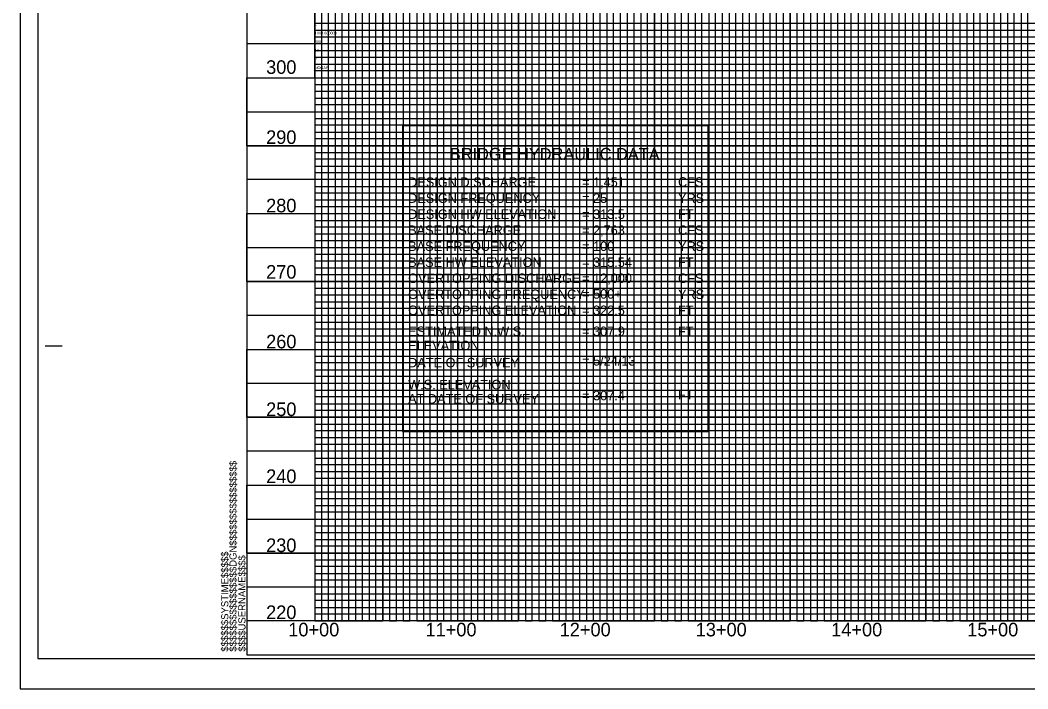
# Model space of a CAD drawing. Extents: x 574125 to 576234, y -56630 to -55530.
# Drawn here: x 574340 to 575082, y -56630 to -56137 of the extents above; entities that cross this region are included whole.
import ezdxf

# ---------------------------------------------------------------- set-up
doc = ezdxf.new("R2010")
doc.units = 0
for name, color, linetype in [('Exist Profile Cell', 7, 'Continuous'), ('Exist Vertical Profile Horizontal Axis Label Major', 7, 'Continuous'), ('Exist Vertical Profile Vertical Axis Label', 7, 'Continuous'), ('Prop Grid Mask', 7, 'Continuous'), ('Prop PFL Text', 7, 'Continuous'), ('Sheet DOT Grid CELL', 7, 'Continuous'), ('Sheet Plot Border Inside CELL', 7, 'Continuous'), ('Sheet Plot Border Outside CELL', 7, 'Continuous'), ('Sheet Profile CELL', 7, 'Continuous'), ('Sheet Profile Grid Major CELL', 7, 'Continuous'), ('Sheet Profile Grid Middle CELL', 7, 'Continuous'), ('Sheet Profile Grid Minor CELL', 7, 'Continuous')]:
    doc.layers.add(name, color=color, linetype=linetype)

msp = doc.modelspace()

# ---------------------------------------------------------------- linework, layer by layer
at = {"layer": 'Exist Profile Cell'}
for q in [(574556.81, -55929.85), (576005.64, -56179.85), (574556.81, -56179.85)]:
    msp.add_line((574556.81, -56179.85), q, dxfattribs=at)
at = {"layer": 'Prop Grid Mask'}
msp.add_lwpolyline([(574621.31, -56440.24), (574846.31, -56440.24), (574846.31, -56215.24), (574621.31, -56215.24)], close=True, dxfattribs=at)
at = {"layer": 'Sheet DOT Grid CELL'}
for p, q in [((574556.81, -55554.85), (574556.81, -56579.85)), ((574606.81, -55554.85), (574606.81, -56579.85)), ((574656.81, -55554.85), (574656.81, -56579.85)), ((574706.81, -55554.85), (574706.81, -56579.85)), ((574756.81, -55554.85), (574756.81, -56579.85)), ((574806.81, -55554.85), (574806.81, -56579.85)), ((574856.81, -55554.85), (574856.81, -56579.85)), ((574906.81, -55554.85), (574906.81, -56579.85)), ((574956.81, -55554.85), (574956.81, -56579.85)), ((575006.81, -55554.85), (575006.81, -56579.85)), ((575056.81, -55554.85), (575056.81, -56579.85)), ((574506.81, -56179.85), (576006.81, -56179.85)), ((574506.81, -56229.85), (576006.81, -56229.85)), ((574506.81, -56279.85), (576006.81, -56279.85)), ((574506.81, -56329.85), (576006.81, -56329.85)), ((574506.81, -56379.85), (576006.81, -56379.85)), ((574506.81, -56429.85), (576006.81, -56429.85)), ((574506.81, -56479.85), (576006.81, -56479.85)), ((574506.81, -56529.85), (576006.81, -56529.85))]:
    msp.add_line(p, q, dxfattribs=at)
at = {"layer": 'Sheet Plot Border Inside CELL'}
msp.add_lwpolyline([(576019.31, -55552.3), (574352.81, -55552.3), (574352.81, -56607.4), (576019.31, -56607.4)], close=True, dxfattribs=at)
at = {"layer": 'Sheet Plot Border Outside CELL'}
msp.add_lwpolyline([(576023.81, -55529.85), (574339.81, -55529.85), (574339.81, -56629.85), (576023.81, -56629.85)], close=True, dxfattribs=at)
at = {"layer": 'Sheet Profile CELL'}
for p, q in [((574339.81, -55529.85), (574339.81, -56629.85)), ((574358.31, -56377.35), (574370.81, -56377.35)), ((576006.81, -56579.85), (574506.81, -56579.85)), ((574506.81, -56604.85), (574506.81, -56604.85)), ((574506.81, -56604.85), (574506.81, -56604.85)), ((574506.81, -56604.85), (574506.81, -56604.85)), ((574506.81, -56604.85), (574506.81, -56604.85)), ((574506.81, -56604.85), (574506.81, -56604.85)), ((574506.81, -56604.85), (574506.81, -56604.85)), ((574339.81, -56629.85), (576023.81, -56629.85))]:
    msp.add_line(p, q, dxfattribs=at)
msp.add_lwpolyline([(576006.81, -55554.85), (574506.81, -55554.85), (574506.81, -56604.85), (576006.81, -56604.85)], close=True, dxfattribs=at)
msp.add_lwpolyline([(574544.31, -56604.85), (574544.31, -56604.85)], dxfattribs=at)
at = {"layer": 'Sheet Profile Grid Major CELL'}
for points in [[(574506.81, -55554.85), (574556.81, -55554.85), (574556.81, -56579.85), (574606.81, -56579.85), (574606.81, -55554.85), (574656.81, -55554.85), (574656.81, -56579.85), (574706.81, -56579.85), (574706.81, -55554.85), (574756.81, -55554.85), (574756.81, -56579.85), (574806.81, -56579.85), (574806.81, -55554.85), (574856.81, -55554.85), (574856.81, -56579.85), (574906.81, -56579.85), (574906.81, -55554.85), (574956.81, -55554.85), (574956.81, -56579.85), (575006.81, -56579.85), (575006.81, -55554.85), (575056.81, -55554.85), (575056.81, -56579.85), (575106.81, -56579.85)], [(576006.81, -56229.85), (574506.81, -56229.85), (574506.81, -56179.85), (576006.81, -56179.85)], [(576006.81, -56329.85), (574506.81, -56329.85), (574506.81, -56279.85), (576006.81, -56279.85)], [(576006.81, -56429.85), (574506.81, -56429.85), (574506.81, -56379.85), (576006.81, -56379.85)], [(576006.81, -56529.85), (574506.81, -56529.85), (574506.81, -56479.85), (576006.81, -56479.85)]]:
    msp.add_lwpolyline(points, dxfattribs=at)
at = {"layer": 'Sheet Profile Grid Middle CELL'}
for points in [[(574581.81, -56579.85), (574581.81, -55554.85), (574631.81, -55554.85), (574631.81, -56579.85), (574681.81, -56579.85), (574681.81, -55554.85), (574731.81, -55554.85), (574731.81, -56579.85), (574781.81, -56579.85), (574781.81, -55554.85), (574831.81, -55554.85), (574831.81, -56579.85), (574881.81, -56579.85), (574881.81, -55554.85), (574931.81, -55554.85), (574931.81, -56579.85), (574981.81, -56579.85), (574981.81, -55554.85), (575031.81, -55554.85), (575031.81, -56579.85), (575081.81, -56579.85), (575081.81, -55554.85), (575131.81, -55554.85)], [(576006.81, -56154.85), (574506.81, -56154.85), (574506.81, -56204.85), (576006.81, -56204.85)], [(576006.81, -56254.85), (574506.81, -56254.85), (574506.81, -56304.85), (576006.81, -56304.85)], [(576006.81, -56354.85), (574506.81, -56354.85), (574506.81, -56404.85), (576006.81, -56404.85)], [(576006.81, -56454.85), (574506.81, -56454.85), (574506.81, -56504.85), (576006.81, -56504.85)], [(576006.81, -56554.85), (574506.81, -56554.85)]]:
    msp.add_lwpolyline(points, dxfattribs=at)
at = {"layer": 'Sheet Profile Grid Minor CELL'}
for points in [[(574561.81, -55554.85), (574561.81, -56579.85), (574566.81, -56579.85), (574566.81, -55554.85)], [(574571.81, -55554.85), (574571.81, -56579.85), (574576.81, -56579.85), (574576.81, -55554.85)], [(574586.81, -55554.85), (574586.81, -56579.85), (574591.81, -56579.85), (574591.81, -55554.85)], [(574596.81, -55554.85), (574596.81, -56579.85), (574601.81, -56579.85), (574601.81, -55554.85)], [(574611.81, -55554.85), (574611.81, -56579.85), (574616.81, -56579.85), (574616.81, -55554.85)], [(574621.81, -55554.85), (574621.81, -56579.85), (574626.81, -56579.85), (574626.81, -55554.85)], [(574636.81, -55554.85), (574636.81, -56579.85), (574641.81, -56579.85), (574641.81, -55554.85)], [(574646.81, -55554.85), (574646.81, -56579.85), (574651.81, -56579.85), (574651.81, -55554.85)], [(574661.81, -55554.85), (574661.81, -56579.85), (574666.81, -56579.85), (574666.81, -55554.85)], [(574671.81, -55554.85), (574671.81, -56579.85), (574676.81, -56579.85), (574676.81, -55554.85)], [(574686.81, -55554.85), (574686.81, -56579.85), (574691.81, -56579.85), (574691.81, -55554.85)], [(574696.81, -55554.85), (574696.81, -56579.85), (574701.81, -56579.85), (574701.81, -55554.85)], [(574711.81, -55554.85), (574711.81, -56579.85), (574716.81, -56579.85), (574716.81, -55554.85)], [(574721.81, -56579.85), (574726.81, -56579.85), (574726.81, -55554.85)], [(574721.81, -55554.85), (574721.81, -56579.85)], [(574736.81, -55554.85), (574736.81, -56579.85), (574741.81, -56579.85), (574741.81, -55554.85)], [(574746.81, -55554.85), (574746.81, -56579.85), (574751.81, -56579.85), (574751.81, -55554.85)], [(574761.81, -55554.85), (574761.81, -56579.85), (574766.81, -56579.85), (574766.81, -55554.85)], [(574771.81, -55554.85), (574771.81, -56579.85), (574776.81, -56579.85), (574776.81, -55554.85)], [(574786.81, -55554.85), (574786.81, -56579.85), (574791.81, -56579.85), (574791.81, -55554.85)], [(574796.81, -55554.85), (574796.81, -56579.85), (574801.81, -56579.85), (574801.81, -55554.85)], [(574811.81, -55554.85), (574811.81, -56579.85), (574816.81, -56579.85), (574816.81, -55554.85)], [(574821.81, -55554.85), (574821.81, -56579.85), (574826.81, -56579.85), (574826.81, -55554.85)], [(574836.81, -55554.85), (574836.81, -56579.85), (574841.81, -56579.85), (574841.81, -55554.85)], [(574846.81, -55554.85), (574846.81, -56579.85), (574851.81, -56579.85), (574851.81, -55554.85)], [(574861.81, -55554.85), (574861.81, -56579.85), (574866.81, -56579.85), (574866.81, -55554.85)], [(574871.81, -55554.85), (574871.81, -56579.85), (574876.81, -56579.85), (574876.81, -55554.85)], [(574886.81, -55554.85), (574886.81, -56579.85), (574901.81, -56579.85), (574901.81, -55554.85)], [(574891.81, -55554.85), (574891.81, -56579.85), (574896.81, -56579.85), (574896.81, -55554.85)], [(574891.81, -55555.45), (574891.81, -56579.85), (574896.81, -56579.85), (574896.81, -55555.45)], [(574911.81, -55554.85), (574911.81, -56579.85), (574916.81, -56579.85), (574916.81, -55554.85)], [(574921.81, -55554.85), (574921.81, -56579.85), (574926.81, -56579.85), (574926.81, -55554.85)], [(574936.81, -55554.85), (574936.81, -56579.85), (574941.81, -56579.85), (574941.81, -55554.85)], [(574946.81, -55554.85), (574946.81, -56579.85), (574951.81, -56579.85), (574951.81, -55554.85)], [(574961.81, -55554.85), (574961.81, -56579.85), (574966.81, -56579.85), (574966.81, -55554.85)], [(574971.81, -55554.85), (574971.81, -56579.85), (574976.81, -56579.85), (574976.81, -55554.85)], [(574986.81, -55554.85), (574986.81, -56579.85), (574991.81, -56579.85), (574991.81, -55554.85)], [(574996.81, -55554.85), (574996.81, -56579.85), (575001.81, -56579.85), (575001.81, -55554.85)], [(575011.81, -55554.85), (575011.81, -56579.85), (575016.81, -56579.85), (575016.81, -55554.85)], [(575021.81, -55554.85), (575021.81, -56579.85), (575026.81, -56579.85), (575026.81, -55554.85)], [(575036.81, -55554.85), (575036.81, -56579.85)], [(575041.81, -55554.85), (575041.81, -56579.85), (575046.81, -56579.85), (575046.81, -55554.85), (575051.81, -55554.85), (575051.81, -56579.85), (575061.81, -56579.85), (575061.81, -55554.85), (575066.81, -55554.85), (575066.81, -56579.85), (575071.81, -56579.85), (575071.81, -55554.85), (575076.81, -55554.85), (575076.81, -56579.85)], [(575956.81, -56139.85), (574556.81, -56139.85), (574556.81, -56144.85), (575956.81, -56144.85)], [(575956.81, -56149.85), (574556.81, -56149.85), (574556.81, -56159.85), (575956.81, -56159.85)], [(575956.81, -56164.85), (574556.81, -56164.85), (574556.81, -56169.85), (575956.81, -56169.85)], [(575956.81, -56174.85), (574556.81, -56174.85), (574556.81, -56184.85), (575956.81, -56184.85)], [(575956.81, -56189.85), (574556.81, -56189.85), (574556.81, -56194.85), (575956.81, -56194.85)], [(575956.81, -56199.85), (574556.81, -56199.85), (574556.81, -56209.85), (575956.81, -56209.85)], [(575956.81, -56214.85), (574556.81, -56214.85), (574556.81, -56219.85), (575956.81, -56219.85)], [(575956.81, -56224.85), (574556.81, -56224.85), (574556.81, -56234.85), (575956.81, -56234.85)], [(575956.81, -56239.85), (574556.81, -56239.85), (574556.81, -56244.85), (575956.81, -56244.85)], [(575956.81, -56249.85), (574556.81, -56249.85), (574556.81, -56259.85), (575956.81, -56259.85)], [(575956.81, -56264.85), (574556.81, -56264.85), (574556.81, -56269.85), (575956.81, -56269.85)], [(575956.81, -56274.85), (574556.81, -56274.85), (574556.81, -56284.85), (575956.81, -56284.85)], [(575956.81, -56289.85), (574556.81, -56289.85), (574556.81, -56294.85), (575956.81, -56294.85)], [(575956.81, -56299.85), (574556.81, -56299.85), (574556.81, -56309.85), (575956.81, -56309.85)], [(575956.81, -56314.85), (574556.81, -56314.85), (574556.81, -56319.85), (575956.81, -56319.85)], [(575956.81, -56324.85), (574556.81, -56324.85), (574556.81, -56334.85), (575956.81, -56334.85)], [(575956.81, -56339.85), (574556.81, -56339.85), (574556.81, -56344.85), (575956.81, -56344.85)], [(575956.81, -56349.85), (574556.81, -56349.85), (574556.81, -56359.85), (575956.81, -56359.85)], [(575956.81, -56364.85), (574556.81, -56364.85), (574556.81, -56369.85), (575956.81, -56369.85)], [(575956.81, -56374.85), (574556.81, -56374.85)], [(574556.81, -56384.85), (575956.81, -56384.85)], [(575956.81, -56389.85), (574556.81, -56389.85), (574556.81, -56394.85), (575956.81, -56394.85)], [(575956.81, -56399.85), (574556.81, -56399.85)], [(574556.81, -56409.85), (575956.81, -56409.85)], [(575956.81, -56414.85), (574556.81, -56414.85), (574556.81, -56419.85), (575956.81, -56419.85)], [(575956.81, -56424.85), (574556.81, -56424.85), (574556.81, -56434.85), (575956.81, -56434.85)], [(575956.81, -56439.85), (574556.81, -56439.85), (574556.81, -56444.85), (575956.81, -56444.85)], [(575956.81, -56449.85), (574556.81, -56449.85), (574556.81, -56459.85), (575956.81, -56459.85)], [(575956.81, -56464.85), (574556.81, -56464.85), (574556.81, -56469.85), (575956.81, -56469.85)], [(575956.81, -56474.85), (574556.81, -56474.85), (574556.81, -56484.85), (575956.81, -56484.85)], [(575956.81, -56489.85), (574556.81, -56489.85), (574556.81, -56494.85), (575956.81, -56494.85)], [(575956.81, -56499.85), (574556.81, -56499.85), (574556.81, -56509.85), (575956.81, -56509.85)], [(575956.81, -56514.85), (574556.81, -56514.85), (574556.81, -56519.85), (575956.81, -56519.85)], [(575956.81, -56524.85), (574556.81, -56524.85), (574556.81, -56534.85), (575956.81, -56534.85)], [(575956.81, -56539.85), (574556.81, -56539.85), (574556.81, -56544.85), (575956.81, -56544.85)], [(575956.81, -56549.85), (574556.81, -56549.85), (574556.81, -56559.85), (575956.81, -56559.85)], [(575956.81, -56564.85), (574556.81, -56564.85), (574556.81, -56569.85), (575956.81, -56569.85)], [(575956.81, -56574.85), (574556.81, -56574.85)]]:
    msp.add_lwpolyline(points, dxfattribs=at)

# ---------------------------------------------------------------- texts
at = {"layer": 'Exist Profile Cell'}
for s, p in [('L', (574556.81, -56141.6)), ('1000.000000', (574556.81, -56147.97)), ('300', (574556.81, -56154.35)), ('10', (574556.81, -56160.72)), ('2', (574556.81, -56167.1)), ('NOGAP', (574556.81, -56173.47))]:
    msp.add_text(s, height=2, dxfattribs=at).set_placement(p)
at = {"layer": 'Exist Vertical Profile Horizontal Axis Label Major'}
for s, p in [('10+00', (574537.24, -56591.2)), ('11+00', (574638.3, -56591.2)), ('12+00', (574737.08, -56591.2)), ('13+00', (574837.24, -56591.2)), ('14+00', (574937.03, -56591.2)), ('15+00', (575037.19, -56591.2))]:
    msp.add_text(s, height=10, rotation=360, dxfattribs=at).set_placement(p)
at = {"layer": 'Exist Vertical Profile Vertical Axis Label'}
for s, p in [('300', (574520.93, -56176.98)), ('290', (574520.93, -56228.58)), ('280', (574520.93, -56278.94)), ('270', (574520.93, -56327.78)), ('260', (574520.93, -56379.12)), ('250', (574520.93, -56428.95)), ('240', (574520.93, -56478.29)), ('230', (574520.93, -56529.12)), ('220', (574520.93, -56578.46))]:
    msp.add_text(s, height=10, rotation=360, dxfattribs=at).set_placement(p)
at = {"layer": 'Prop PFL Text'}
for s, height, p in [('BRIDGE HYDRAULIC DATA', 9, (574656.21, -56240.49)), ('DESIGN DISCHARGE', 7, (574625.51, -56260.19)), ('= 1,451', 7, (574753.58, -56260.19)), ('CFS', 7, (574824.22, -56260.09)), ('DESIGN FREQUENCY', 7, (574625.51, -56271.99)), ('= 25', 7, (574753.58, -56271.99)), ('YRS', 7, (574824.22, -56271.99)), ('DESIGN HW ELEVATION', 7, (574625.51, -56283.79)), ('= 313.5', 7, (574753.58, -56283.79)), ('FT', 7, (574824.22, -56283.79)), ('BASE DISCHARGE', 7, (574625.51, -56295.59)), ('= 2,763', 7, (574753.58, -56295.59)), ('CFS', 7, (574824.22, -56295.59)), ('BASE FREQUENCY', 7, (574625.51, -56307.39)), ('= 100', 7, (574753.58, -56307.39)), ('YRS', 7, (574824.22, -56307.39)), ('BASE HW ELEVATION', 7, (574625.51, -56319.19)), ('= 315.54', 7, (574753.58, -56319.19)), ('FT', 7, (574824.22, -56319.19)), ('OVERTOPPING DISCHARGE', 7, (574625.51, -56330.99)), ('= 12,000', 7, (574753.58, -56330.99)), ('CFS', 7, (574824.22, -56330.99)), ('OVERTOPPING FREQUENCY', 7, (574625.51, -56342.79)), ('= 500+', 7, (574753.58, -56342.5)), ('YRS', 7, (574824.22, -56342.79)), ('OVERTOPPING ELEVATION', 7, (574625.51, -56354.59)), ('= 322.5', 7, (574753.58, -56354.59)), ('FT', 7, (574824.22, -56354.59)), ('ESTIMATED N.W.S.', 7, (574625.51, -56370.04)), ('= 307.9', 7, (574753.58, -56370.04)), ('FT', 7, (574824.22, -56370.04)), ('ELEVATION', 7, (574625.51, -56380.54)), ('= 5/24/13', 7, (574753.58, -56391.79)), ('DATE OF SURVEY', 7, (574625.51, -56393.09)), ('W.S. ELEVATION', 7, (574625.51, -56409.29)), ('AT DATE OF SURVEY', 7, (574625.51, -56419.79)), ('= 307.4', 7, (574753.58, -56417.34)), ('FT', 7, (574824.22, -56416.74))]:
    msp.add_text(s, height=height, dxfattribs=at).set_placement(p)
at = {"layer": 'Sheet Profile CELL'}
for s, p in [('$$$$$$$$$$$$$$$$DGN$$$$$$$$$$$$$$$$', (574499.16, -56602.48)), ('$$$$$$SYSTIME$$$$$', (574493.11, -56602.48)), ('$$$$USERNAME$$$$', (574505.73, -56602.47))]:
    msp.add_text(s, height=5.25, rotation=90, dxfattribs=at).set_placement(p)

doc.saveas('drawing.dxf')
